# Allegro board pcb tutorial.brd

Outline 100 x 50 mm; copper layers: TOP, POWERPLANE_1, BOTTOM. Coordinates in mm from the lower left corner of the outline.
Outline path: rectangle 0,0 100,50

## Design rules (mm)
constraint set DEFAULT: min track width 0.28
net group DPD: nets D+ D-

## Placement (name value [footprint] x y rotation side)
C1  100uF  [1210]  9 28 0 top
C2  10uF  [0402-CAP]  15 35 270 top
C3  10uF  [0402-CAP]  34 8 180 top
C4  0.1uF  [0402-CAP]  6 23 0 top
C5  0.1uF  [0402-CAP]  6 20 0 top
C6  0.1uF  [0402-CAP]  8 40 90 top
C7  0.1uF  [0402-CAP]  36 16 90 top
C8  0.1uF  [0402-CAP]  5 40 90 top
C9  10uF  [0402-CAP]  15 24 180 top
IC1  PIC32MX440F512H  [SQFP-S-10X10-64]  24 26 90 top
JP1  -  [XTEND-DIGI-MODEM]  69 25 0 top
JP2  PIC 32 PROG  [1X06_LOCK]  16 12 0 top
MAIN_PWR  LED  [LED_LNJ]  24 4 90 top
NOREF  -  [unnamed]  96 4 0 top
NOREF#2  -  [#2]  0 50 0 top
NOREF#3  -  [#2]  0 0 90 top
NOREF#4  -  [unnamed]  4 4 0 top
NOREF#5  -  [unnamed]  4 46 0 top
NOREF#6  -  [#2]  -23 -96 0 top
NOREF#7  -  [unnamed]  96 46 0 top
R1  150  [0402-RES]  20 4 90 top
R2  56k  [0402-RES]  34 11 180 top
U1  LT1965EMS8E-1P5TRPBF  [MSOP-EP08_3X3_ADI]  9 34 0 top
X1  USB-B  [USB-MICROB]  26 46 180 top
Y1  8MHz  [CRYSTAL-SMD]  16 41 270 top

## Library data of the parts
C1-C9 = CAP NP
IC1 = PIC32MX440F512H
JP1 = XTEND-DIGI-MODEM
JP2 = M06_LOCK
MAIN_PWR = LED
R1 R2 = RESISTOR
U1 = LT1965EMS8E-1P5TRPBF_0
X1 = USB-MICROB
Y1 = CRYSTAL

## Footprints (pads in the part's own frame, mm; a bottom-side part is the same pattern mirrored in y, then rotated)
1X06_LOCK
  round 1.88 hole 1.016: 1(0,0) 2(2.54,-0.254) 3(5.08,0) 4(7.62,-0.254) 5(10.16,0) 6(12.7,-0.254)
0402-CAP
  rect 0.7x0.9 smd: 1(-0.65,0) 2(0.65,0)
0402-RES
  rect 0.7x0.9 smd: 1(-0.65,0) 2(0.65,0)
1210
  rect 1.2x2 smd: 1(-1.6,0) 2(1.6,0)
CRYSTAL-SMD
  rect 1.1x1.9 smd: 1(-1.15,1.85) 2(-1.15,-1.85) 3(1.15,-1.85) 4(1.15,1.85)
LED_LNJ
  rect 0.445x0.95 smd: 1(-0.652,0) 2(0.652,0)
MSOP-EP08_3X3_ADI
  rect 1.397x0.432 smd: 1(-2.197,0.975) 2(-2.197,0.325) 3(-2.197,-0.325) 4(-2.197,-0.975) 5(2.197,-0.975) 6(2.197,-0.325) 7(2.197,0.325) 8(2.197,0.975)
  rect 1.676x1.88 smd: EPAD(0,0)
SQFP-S-10X10-64
  rect 1.6x0.295 smd: 1(-5.6,3.75) 2(-5.6,3.25) 3(-5.6,2.75) 4(-5.6,2.25) 5(-5.6,1.75) 6(-5.6,1.25) 7(-5.6,0.75) 8(-5.6,0.25) 9(-5.6,-0.25) 10(-5.6,-0.75) 11(-5.6,-1.25) 12(-5.6,-1.75) 13(-5.6,-2.25) 14(-5.6,-2.75) 15(-5.6,-3.25) 16(-5.6,-3.75) 33(5.6,-3.75) 34(5.6,-3.25) 35(5.6,-2.75) 36(5.6,-2.25) 37(5.6,-1.75) 38(5.6,-1.25) 39(5.6,-0.75) 40(5.6,-0.25) 41(5.6,0.25) 42(5.6,0.75) 43(5.6,1.25) 44(5.6,1.75) 45(5.6,2.25) 46(5.6,2.75) 47(5.6,3.25) 48(5.6,3.75)
  rect 0.295x1.6 smd: 17(-3.75,-5.6) 18(-3.25,-5.6) 19(-2.75,-5.6) 20(-2.25,-5.6) 21(-1.75,-5.6) 22(-1.25,-5.6) 23(-0.75,-5.6) 24(-0.25,-5.6) 25(0.25,-5.6) 26(0.75,-5.6) 27(1.25,-5.6) 28(1.75,-5.6) 29(2.25,-5.6) 30(2.75,-5.6) 31(3.25,-5.6) 32(3.75,-5.6) 49(3.75,5.6) 50(3.25,5.6) 51(2.75,5.6) 52(2.25,5.6) 53(1.75,5.6) 54(1.25,5.6) 55(0.75,5.6) 56(0.25,5.6) 57(-0.25,5.6) 58(-0.75,5.6) 59(-1.25,5.6) 60(-1.75,5.6) 61(-2.25,5.6) 62(-2.75,5.6) 63(-3.25,5.6) 64(-3.75,5.6)
unnamed
  round 4.064 hole 3.81: (0,0)
USB-MICROB
  rect 0.35x1.4 smd: D+(0,2.65) D-(-0.65,2.65) GND(1.3,2.65) ID(0.65,2.65) VBUS(-1.3,2.65)
  rect 1.8x1.9 smd: MT1(-3.8,0) MT2(3.8,0)
  rect 2.1x1.6 smd: MT3(-3.1,2.55) MT4(3.1,2.55)
  rect 1.9x1.9 smd: P_1(-1.2,0) P_2(1.2,0)
XTEND-DIGI-MODEM
  round 0 hole 3.3 unplated: (-26.5,14.5) (-26.5,-14.5) (26.5,14.5) (26.5,-14.5)
  round 1.422 hole 0.7: 1(-27.5,9) 2(-25.5,9) 3(-27.5,7) 4(-25.5,7) 5(-27.5,5) 6(-25.5,5) 7(-27.5,3) 8(-25.5,3) 9(-27.5,1) 10(-25.5,1) 11(-27.5,-1) 12(-25.5,-1) 13(-27.5,-3) 14(-25.5,-3) 15(-27.5,-5) 16(-25.5,-5) 17(-27.5,-7) 18(-25.5,-7) 19(-27.5,-9) 20(-25.5,-9)

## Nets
3.3V: C1.1 C4.1 C5.1 C6.1 C7.1 C8.1 IC1.10 IC1.19 IC1.26 IC1.35 IC1.38 JP2.2 R1.1 R2.2 U1.1 U1.2 U1.3
GND: C1.2 C2.2 C3.2 C4.2 C5.2 C6.2 C7.2 C8.2 C9.2 IC1.9 IC1.20 IC1.25 IC1.41 JP1.1 JP2.3 MAIN_PWR.1(CATHODE) U1.4 U1.5 U1.EPAD X1.GND Y1.2 Y1.4(GND_4)
VBUS: C2.1 IC1.34 JP1.2(VCC) U1.6(SHDN) U1.7 U1.8 X1.VBUS
CTS: IC1.21 JP1.9
D+: IC1.37 X1.D+
D-: IC1.36 X1.D-
PROG0: IC1.17 JP2.5
PROG1: IC1.18 JP2.4
RESET: IC1.7(_MCLR) JP2.1
RTS: IC1.29 JP1.10
SHDN: IC1.59 JP1.7
URX: IC1.31 JP1.6
UTX: IC1.32 JP1.5
N02210: C3.1 JP1.11 R2.1
N02258: IC1.39 Y1.1
N02262: IC1.40 Y1.3
N02281: C9.1 IC1.56
N02349: MAIN_PWR.2 R1.2

Pads without a net: IC1 1 2 3 4 5 6 8 11 12 13 14 15 16 22 23 24 27 28 30 33 42 43 44 45 46 47 48 49 50 51 52 53 54 55 57 58 60 61 62 63 64; JP1 3 4 8 12 13 14 15 16 17 18 19 20; JP2 6; X1 ID MT1 MT2 MT3 MT4 P_1 P_2

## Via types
v1: diameter 0.61, hole 0.33, TOP to BOTTOM, 34 vias

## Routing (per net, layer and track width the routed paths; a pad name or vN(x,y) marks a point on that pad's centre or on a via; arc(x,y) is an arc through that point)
3.3V: length 21.1
  TOP w0.28: IC1.19 v1(31.37,23.25) ; IC1.26 v1(30.83,26.75) ; IC1.35 v1(26.75,32.83) ; IC1.10 v1(24.75,18.63) ; IC1.38 v1(25.25,32.83)
  TOP w0.381: C4.1 v1(4.57,23) ; 6.31,34.98 v1(5.67,34.98) ; 6.31,34.98 6.31,34.44 6.42,34.33 U1.2 U1.3 ; 6.31,34.98 U1.1 ; C5.1 v1(4.57,20) ; C7.1 v1(36,14.57) ; C8.1 v1(5,38.57) ; R2.2 v1(32.57,11) ; C1.1 v1(6.37,28) ; R1.1 v1(20,2.57) ; C6.1 v1(8,38.57)
  POWERPLANE_1 w0.381: JP2.2 19.66,11.75 ; JP2.2 17.42,11.75 ; JP2.2 18.54,10.63 ; JP2.2 18.54,12.86
GND: length 33.3
  TOP w0.28: IC1.20 v1(26.27,23.75) ; IC1.9 v1(24.25,22.34) ; IC1.25 v1(26.27,26.25) ; IC1.41 v1(23.75,29.96)
  TOP w0.381: MAIN_PWR.1 v1(24,2.69) ; U1.5 v1(12.33,33.02) ; U1.EPAD v1(9,35.37) ; C7.2 v1(36,17.43) ; C3.2 v1(32.57,8) ; C2.2 v1(15,33.57) ; C5.2 v1(7.43,20) ; C1.2 v1(11.63,28) ; C6.2 v1(8,41.43) ; C4.2 v1(7.43,23) ; C9.2 v1(13.57,24) ; X1.GND v1(24.7,42.22) ; Y1.4 v1(19.23,39.85) ; U1.4 v1(5.67,33.02) ; C8.2 v1(5,41.43) ; Y1.2 v1(14.15,43.13)
  BOTTOM w0.381: JP1.1 42.39,34 ; JP1.1 41.5,33.11 ; JP1.1 41.5,34.89 ; JP1.1 40.61,34 ; JP2.3 21.08,13.12 ; JP2.3 19.96,12 ; JP2.3 21.08,10.88 ; JP2.3 22.2,12
VBUS: length 51.2
  TOP w0.28: 27.25,36.17 41.33,36.17 JP1.2 ; 27.25,36.17 27.25,42.33 27.3,42.38 X1.VBUS ; 27.25,36.17 27.25,33.14 27.32,33.07 27.32,31.67 IC1.34 27.25,29.95 26.69,29.39 21.13,29.39 15.72,34.81 15.72,35.03 15.1,35.65 C2.1 14.97,35.68 14.21,35.68 13.5,34.98 U1.8 U1.7 U1.6
CTS: length 12.6
  TOP w0.28: IC1.21 32.62,24.25 34.37,26 JP1.9
D+: length 11.9
  TOP w0.127: IC1.37 25.75,41.63 26,41.88 X1.D+
D-: length 12.1
  TOP w0.127: IC1.36 26.25,32.59 26,32.84 26,41.53 26.65,42.17 X1.D-
PROG0: length 11.7
  TOP w0.28: IC1.17 29.6,15.44 JP2.5
PROG1: length 14
  TOP w0.28: JP2.4 28.53,16.66 28.53,22.51 28.77,22.75 IC1.18
RESET: length 11.4
  TOP w0.28: JP2.1 23.25,19.25 IC1.7
RTS: length 14.8
  TOP w0.28: JP1.10 42.52,26.98 31.94,26.98 30.67,28.25 IC1.29
SHDN: length 33.3
  TOP w0.28: JP1.7 42.12,28 43.09,28.98 43.86,28.98 44.48,29.59 44.48,30.41 43.91,30.98 29.19,30.98 22.96,24.75 IC1.59
URX: length 14.4
  TOP w0.28: JP1.6 42.52,29.02 30.9,29.02 30.67,29.25 IC1.31
UTX: length 12
  TOP w0.28: IC1.32 40.27,29.75 40.52,30 JP1.5
N02210: length 18.8
  TOP w0.28: JP1.11 34.65,17.15 R2.1 C3.1
N02258: length 14.2
  TOP w0.28: IC1.39 24.68,31.67 24.68,36.64 19.16,42.15 Y1.1
N02262: length 14.9
  TOP w0.28: IC1.40 24.25,33.89 23.09,35.05 19.35,35.05 14.55,39.85 Y1.3
N02281: length 4.2
  TOP w0.28: IC1.56 17.57,26.25 17.33,26.01 17.33,25.07 16.27,24 C9.1
N02349: length 4
  TOP w0.28: MAIN_PWR.2 20.72,4.65 20.72,4.65 R1.2

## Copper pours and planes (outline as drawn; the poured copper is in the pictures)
3.3V on POWERPLANE_1: 0.3,49.7 99.7,49.7 99.7,0.3 0.3,0.3
GND on BOTTOM: 0.3,49.7 99.7,49.7 99.7,0.3 0.3,0.3

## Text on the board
User.Comments: A | EMA Design Automation | 225 Tech Park Drive | Rochester, NY, 14623 | EMA-123 | 1 of 1
XSECTION_CHART: *  SURFACE | L1 TOP CONDUCTOR | *  DIELECTRIC | L2 POWERPLANE_1 PLANE | L3 BOTTOM CONDUCTOR | DESIGN CROSS SECTION CHART | ___________________________ | TOTAL THICKNESS 0.49784 MM | 1-3
DIMENSION: FIGURE | FINISHED_SIZE | 0.3302 | 0.7 | 1.016 | 3.81 | 3.3 | DRILL CHART: TOP to BOTTOM | ALL UNITS ARE IN MILLIMETERS | PLATED | NON-PLATED | QTY | 34 | 20 | 6 | 4
